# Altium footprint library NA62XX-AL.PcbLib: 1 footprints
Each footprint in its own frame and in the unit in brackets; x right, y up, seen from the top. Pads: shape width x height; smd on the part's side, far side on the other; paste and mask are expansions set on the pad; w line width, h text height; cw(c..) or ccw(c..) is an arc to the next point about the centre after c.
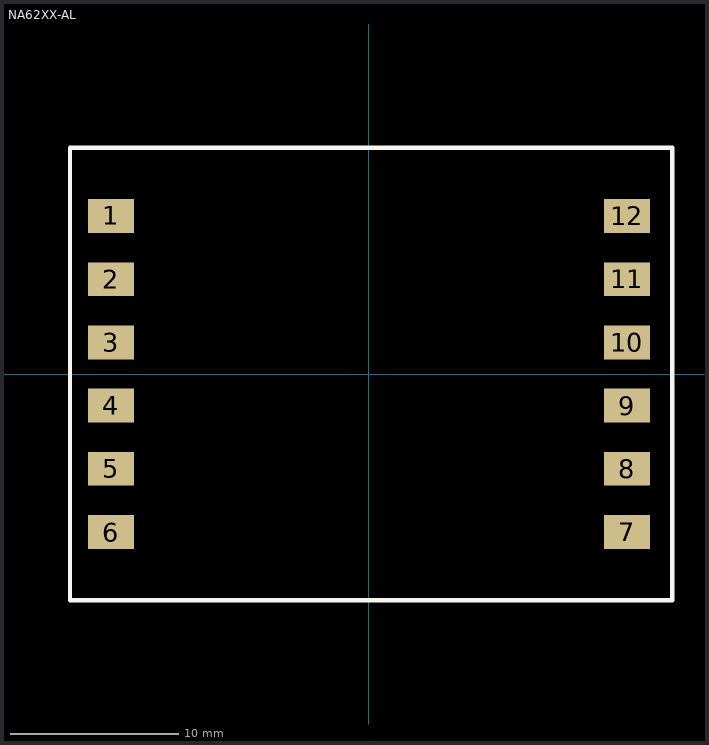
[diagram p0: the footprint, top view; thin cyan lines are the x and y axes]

## NA62XX-AL [mil] "COILCRAFT TRANFORMER"
height 560
pads (13):
  round 60 on Top Overlay: 0(-750,370)
  rect 108x79 smd: 1(-604,370) 2(-604,222) 3(-604,74) 4(-604,-74) 5(-604,-222) 6(-604,-370) 7(604,-370) 8(604,-222) 9(604,-74) 10(604,74) 11(604,222) 12(604,370)
Top Overlay:
  lines w10: -700,-530 -700,530 710,530 710,-530 -700,-530
M5 Assembly Top:
  text ".Designator" at 0,0 h40
3D body: height 560, standoff 0, extent -700,-530 710,530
